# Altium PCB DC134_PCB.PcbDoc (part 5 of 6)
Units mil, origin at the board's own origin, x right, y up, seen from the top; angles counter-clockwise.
Board outline 4000 x 2750 mil, 6 copper layers (L1_Top Layer, L2_GND1, L3_Signal, L4_Plane, L5_GND2, L6_Bottom Layer), stack 60.4 mil thick; 404 components, 244 nets, 1547 pads, 694 vias.
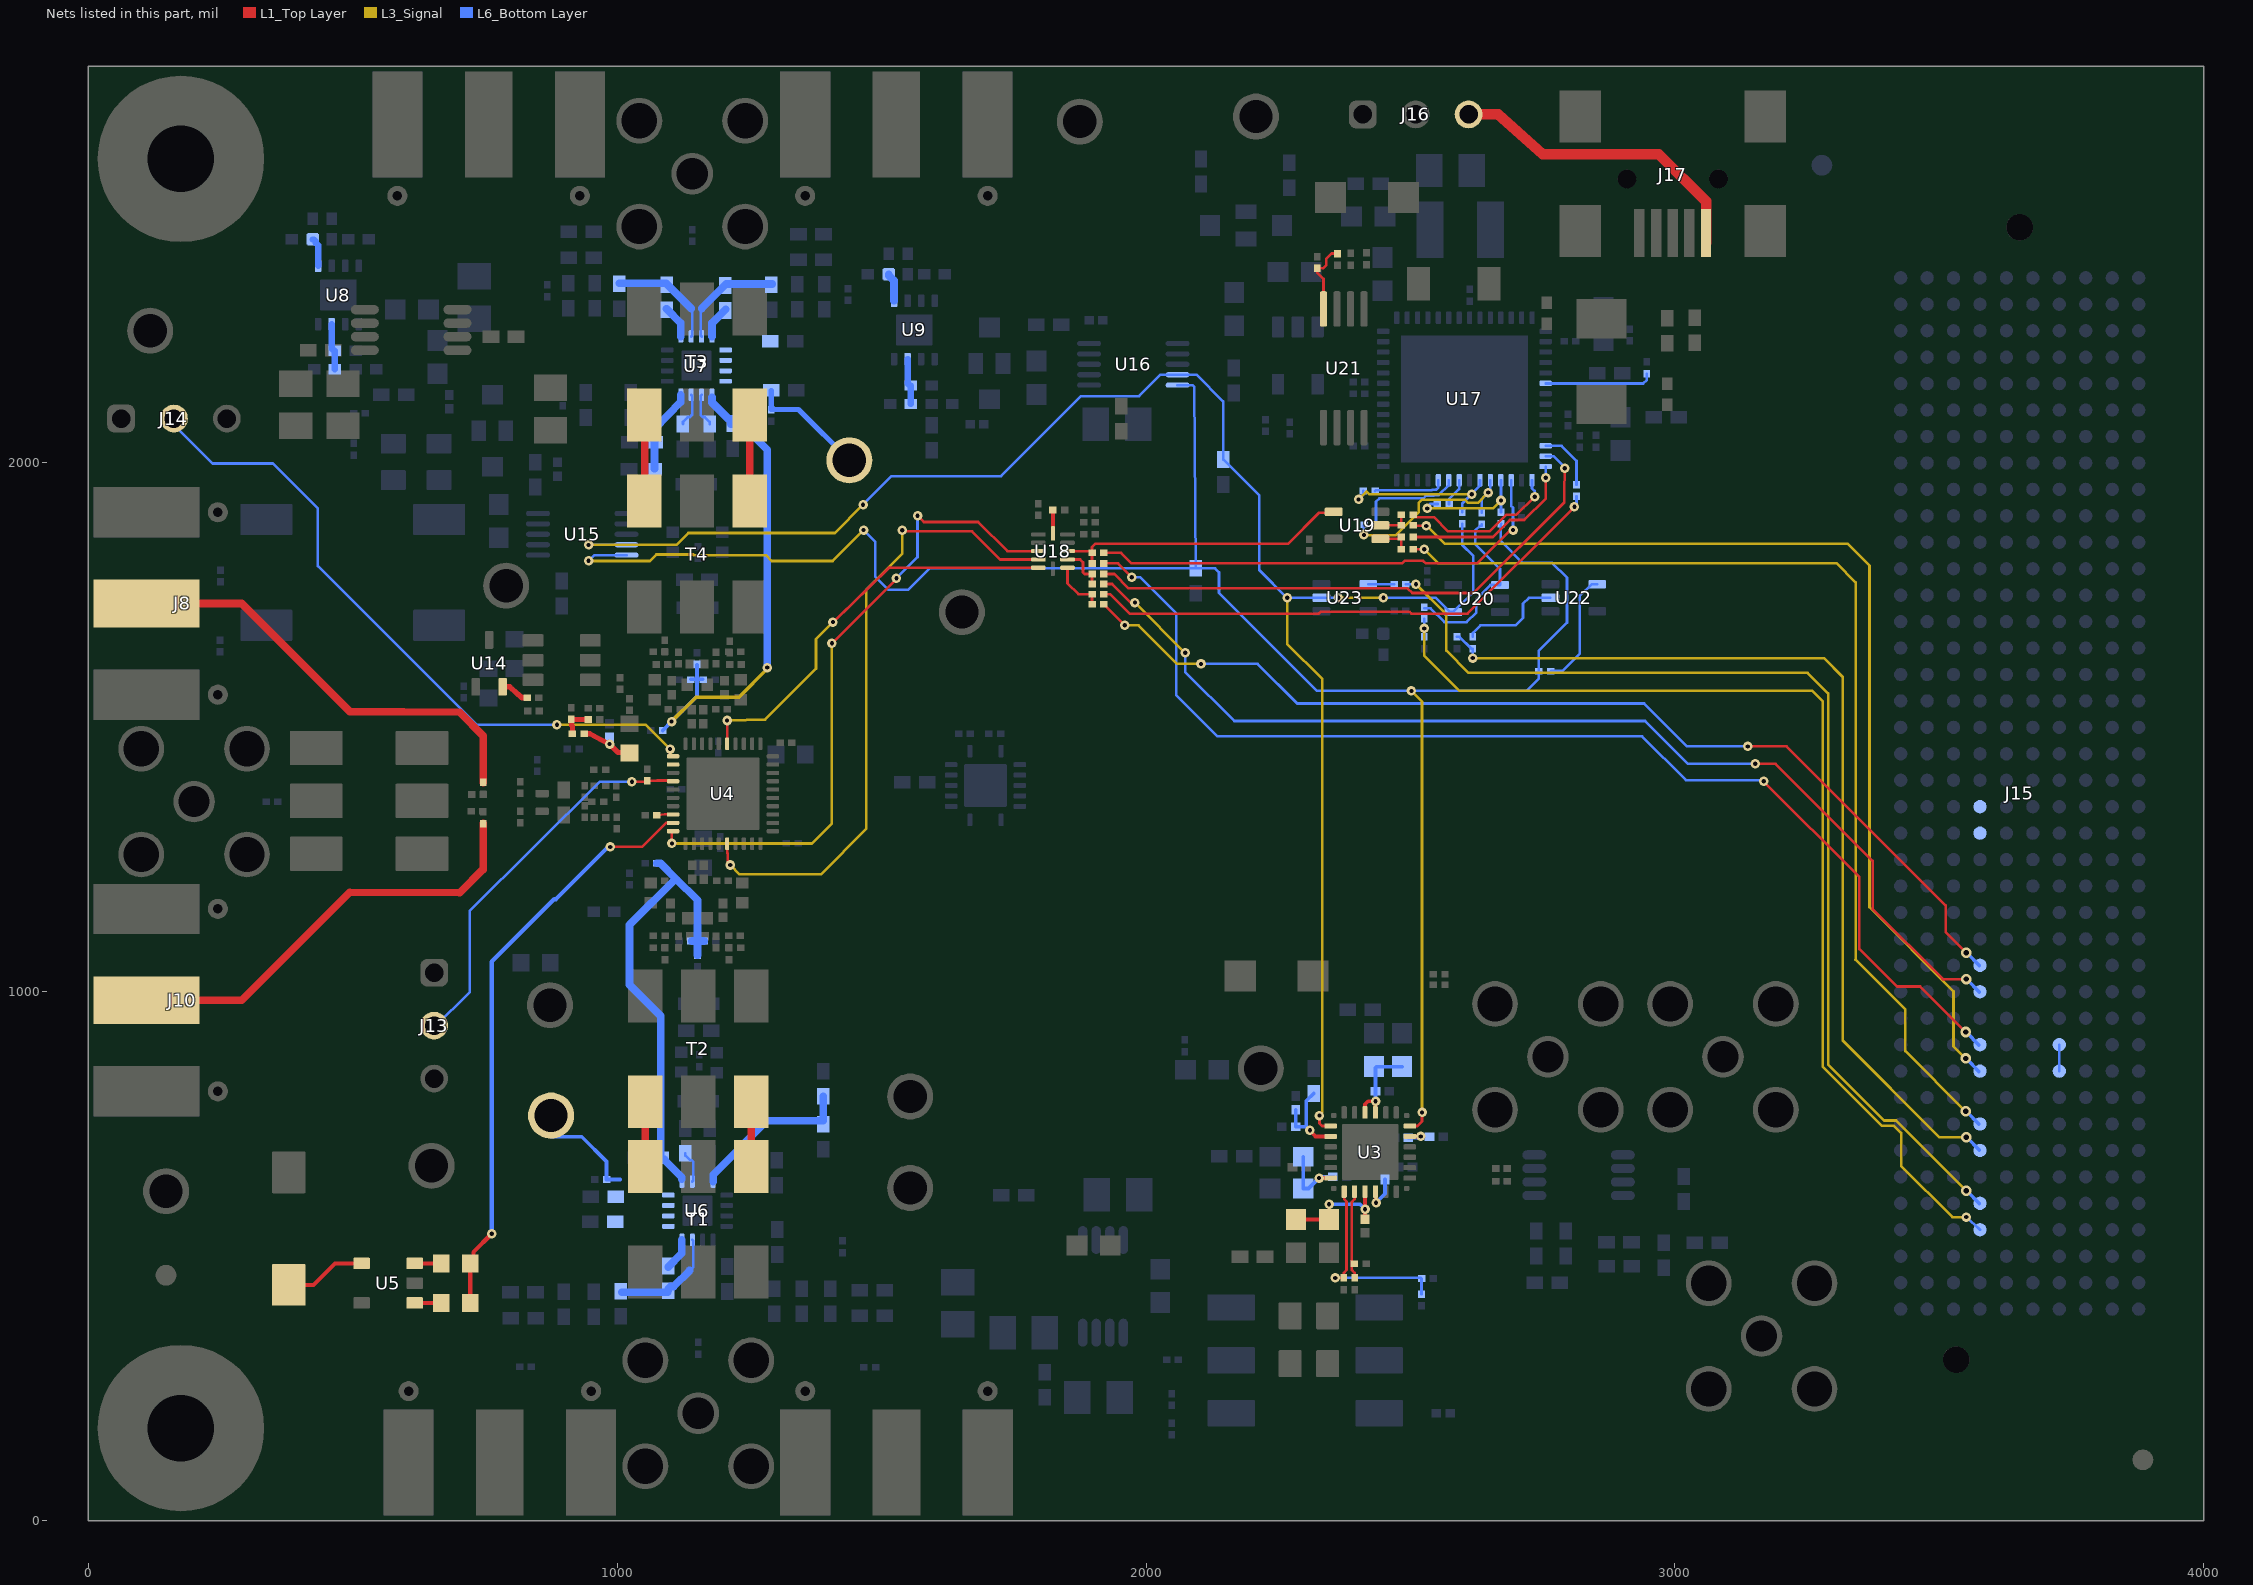
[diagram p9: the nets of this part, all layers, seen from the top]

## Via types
v1: diameter 18, hole 8, L1_Top Layer to L6_Bottom Layer, tented both sides, 448 vias
v2: diameter 20, hole 10, L1_Top Layer to L6_Bottom Layer, tented both sides, 182 vias
v3: diameter 19.68, hole 7.87, L1_Top Layer to L6_Bottom Layer, tented both sides, 42 vias
v4: diameter 19.68, hole 7.87, L1_Top Layer to L6_Bottom Layer, 20 vias
v5: diameter 18, hole 8, L1_Top Layer to L6_Bottom Layer, 2 vias

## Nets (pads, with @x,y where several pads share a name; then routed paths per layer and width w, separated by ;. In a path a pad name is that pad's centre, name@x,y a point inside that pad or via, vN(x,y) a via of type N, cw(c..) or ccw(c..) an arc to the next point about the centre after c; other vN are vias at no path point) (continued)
NetR88_2: R88.2 R96.1 U6.3 | length 207.5
  L6_Bottom Layer w5: 1136.93,472.86 1144,479.93 1144,529.08 U6.3@1142.08,531
  L6_Bottom Layer w14.5: R88.2@1008.45,431.62 R96.1@1095.69,431.62 ; R96.1@1096.8,434.38 1096.8,438.32 1101.36,442.88 1106.95,442.88 1136.93,472.86
NetR90_1: R90.1 U6.10 | length 61.8
  L6_Bottom Layer w5: R90.1@1129,694.38 1129,690.44 1138.31,681.13 1141.07,681.13 1144,678.2 1144,643.16 U6.10@1142.08,641.24
NetR96_2: R96.2 U6.4 | length 62.1
  L6_Bottom Layer w14.5: R96.2@1096.45,479.62 1122.39,505.57 U6.4@1122.39,531
NetR97_1: R97.1 R103.2 U7.2 | length 208.9
  L6_Bottom Layer w5: U7.2@1140,2239.12 1142,2241.12 1142,2290.06 1140,2292.06
  L6_Bottom Layer w14.5: R103.2@1004.32,2339.5 R97.1@1092.56,2339.5 ; R97.1@1093.32,2338.74 1140,2292.06
NetR97_2: R97.2 U7.1 | length 63.6
  L6_Bottom Layer w14.5: R97.2@1093.32,2291.5 1120.32,2264.5 U7.1@1120.32,2239.12
NetR101_1: R101.1 U7.11 | length 65.7
  L6_Bottom Layer w5: R101.1@1124.45,2073.62 1124.45,2077.56 1133.76,2086.87 1137.7,2086.87 1142,2091.17 1142,2126.88 U7.11@1140,2128.88
NetR105_2: R105.2 R113.1 U7.3 | length 206.3
  L6_Bottom Layer w5: U7.3@1159.69,2239.12 1157.79,2241.01 1157.79,2290.22 1159.69,2292.11
  L6_Bottom Layer w14.5: 1159.69,2292.11 R113.1@1205.32,2337.74 ; R113.1@1206.07,2338.5 R105.2@1293.32,2338.5
NetR107_1: R107.1 U7.10 | length 65.4
  L6_Bottom Layer w5: U7.10@1159.69,2128.88 1157.79,2126.99 1157.79,2090.73 1161.65,2086.87 1165.59,2086.87 1174.9,2077.56 R107.1@1174.9,2073.62
NetR113_2: R113.2 U7.4 | length 62.1
  L6_Bottom Layer w14.5: U7.4@1179.37,2239.12 1179.37,2264.55 R113.2@1205.32,2290.5
NetR116_1: R116.1 R121.2 U8.5 | length 55.3
  L6_Bottom Layer w12: R121.2@424.48,2422.62 426.45,2422.62 430.29,2418.78 430.29,2415.94 434.48,2411.75 U8.5@434.48,2372.62
NetR118_1: R118.1 R122.2 U9.5 | length 54.1
  L6_Bottom Layer w15: R118.1@1513.61,2356.65 1513.61,2354.68 1523.61,2344.68 U9.5@1523.61,2306.65
NetR119_1: R119.1 R175.2 U8.3 | length 88.7
  L6_Bottom Layer w12: U8.3@460.07,2262.39 460.07,2223.26 460.36,2222.97 460.36,2216.23 464.2,2212.39 R119.1@466.17,2212.39 R175.2@466.17,2177.39
NetR120_1: R120.1 R176.2 U9.3 | length 88.7
  L6_Bottom Layer w12: U9.3@1549.2,2196.41 1549.2,2157.28 1549.5,2156.99 1549.5,2150.25 1553.34,2146.41 R120.1@1555.31,2146.41 R176.2@1555.31,2111.41
NetR128_2: R128.2 R129.2 R130.1 | length 59.8
  L1_Top Layer w10: R130.1@915.48,1487.98 915.48,1502 913.5,1503.98 R129.2@913.5,1514.95 R128.2@945.48,1514.95
NetR131_1: R131.1 U14.2 | length 54.3
  L1_Top Layer w10: U14.2@783.59,1576.71 797,1576.71 819.98,1556.02 R131.1@829.98,1556.02
NetR135_2: R135.2 R141.2 U18.7 | length 103.2
  L1_Top Layer w5: U18.7@1851.56,1801.8 1851.56,1772.44 1872,1752 R141.2@1897.98,1752 R135.2@1897.98,1733
NetR136_2: R136.2 R142.2 U18.8 | length 88
  L1_Top Layer w5: U18.8@1851.56,1817.54 1875.46,1817.54 1881,1812 1881,1793 1884,1790 R142.2@1897.98,1790 R136.2@1897.98,1771
NetR137_2: R137.2 R143.2 U19.1 | length 57.9
  L1_Top Layer w5: U19.1@2443.29,1856.41 2482.39,1856.41 R137.2@2482.39,1837.59
NetR138_2: R138.2 R144.2 U19.2 | length 59.7
  L1_Top Layer w5: U19.2@2443.29,1882 R138.2@2482.98,1882 R144.2@2482.98,1902
NetR139_2: R139.2 R146.2 U18.9 U19.4 | length 563.1
  L1_Top Layer w5: U18.9@1851.56,1833.29 1894.69,1833.29 R146.2@1897.98,1830 ; R139.2@1897.98,1810 R146.2@1897.98,1830 ; U19.4@2354.71,1907.59 2352.71,1905.59 2326.67,1905.59 2268.07,1847 1904,1847 1897.98,1840.98 R146.2@1897.98,1830
NetR140_1: R140.1 U17.12 | length 115.2
  L6_Bottom Layer w5: U17.12@2755.56,2032.42 2785.58,2032.42 2814,2004 R140.1@2814,1959.02
NetR140_2: R140.2 R141.1 | length 1013.5
  L1_Top Layer w5: R141.1@1920.02,1752 1932,1752 1969,1715 2326.67,1715 2330.17,1718.5 2498.52,1718.5 2502.02,1715 2608,1715 v1(2810,1917)
  L6_Bottom Layer w5: v1(2810,1917) 2814,1921 R140.2@2814,1936.98
NetR142_1: R142.1 U17.13 | length 1067.7
  L1_Top Layer w5: R142.1@1920.02,1790 1940,1790 1967,1763 2494.67,1763 2503.55,1754.11 2619.45,1754.11 2791,1925.67 2791,1942 v1(2792,1990)
  L6_Bottom Layer w5: U17.13@2755.56,2012.73 2770.27,2012.73 2792,1991 v1(2792,1990)
NetR143_1: R143.1 U17.14 | length 341.2
  L1_Top Layer w5: R143.1@2505.02,1860 2656,1860 2688,1892 2693.67,1892 ; 2693.76,1892 2715,1892 2756,1933 v1(2756,1972)
  L6_Bottom Layer w5: U17.14@2755.56,1993.05 2755.56,1986.44 v1(2756,1972)
NetR144_1: R144.1 U17.15 | length 303.4
  L1_Top Layer w5: R144.1@2505.02,1902 2509.52,1897.5 2544.5,1897.5 2571.46,1870.54 2649.57,1870.54 2681.02,1902 2700,1902 v1(2735,1936)
  L6_Bottom Layer w5: U17.15@2730,1967.43 2730,1952 2735,1947 v1(2735,1936)
NetR145_1: R145.1 U17.22 | length 53.8
  L6_Bottom Layer w5: R145.1@2573.02,1921.57 2573.02,1931.53 2592.18,1950.69 U17.22@2592.18,1967.46
NetR145_2: R145.2 R158.1 U17.18 | length 245.4
  L3_Signal w5: v1(2532,1914) 2656.29,1914 v1(2671.29,1929)
  L6_Bottom Layer w5: v1(2532,1914) 2532,1917 v1@2536.57,1921.57 ; R145.2@2550.97,1921.57 v1@2536.57,1921.57 ; R145.2@2551.66,1922.34 2537.34,1922.34 v1@2536.57,1921.57 ; U17.18@2670.92,1967.46 2671.29,1967.08 R158.1@2671.29,1907.02
NetR146_1: R146.1 U17.17 | length 909.8
  L1_Top Layer w5: R146.1@1920.02,1830 1953,1830 1973,1810 2484,1810 2489,1815 2524,1815 2529,1810 2626,1810 2690.78,1874.78 2692.56,1873 v1(2694,1873)
  L6_Bottom Layer w5: U17.17@2690.6,1967.46 2690.6,1919 2694,1915.6 v1(2694,1873)
NetR148_1: R148.1 U17.23 | length 203.5
  L6_Bottom Layer w5: R148.1@2435.02,1883 2435.02,1927 2441.22,1933.2 2524.87,1933.2 2529.81,1938.15 2544.14,1938.15 2545.49,1939.5 2553.5,1939.5 2572.49,1958.49 U17.23@2572.49,1967.46
NetR148_2: R148.2 R159.1 U17.19 | length 372.2
  L3_Signal w5: v1(2412,1864) 2412,1863 2472,1863 2515.5,1906.5 2515.5,1923.83 2522.17,1930.5 2603.17,1930.5 2609.17,1924.5 2627.5,1924.5 v1(2647,1944)
  L6_Bottom Layer w5: v1(2412,1864) 2412,1882.02 R148.2@2412.98,1883 ; R159.1@2635,1906.02 2635,1932 v1(2647,1944) 2651.23,1948.23 U17.19@2651.23,1967.46
NetR149_1: R149.1 U18.12 | length 44.2
  L1_Top Layer w7: U18.12@1824,1866.76 R149.1@1823.98,1911
NetR151_1: R151.1 U17.24 | length 136.5
  L6_Bottom Layer w5: R151.1@2433.02,1947 2434.17,1948.15 2539.99,1948.15 2541.35,1949.5 2548.84,1949.5 2552.8,1953.46 U17.24@2552.8,1967.46
NetR151_2: R151.2 R163.1 U17.20 | length 316.3
  L3_Signal w5: v1(2402,1931) 2417,1946 2422,1941 v1(2616,1941)
  L6_Bottom Layer w5: v1(2402,1931) 2410.98,1939.98 R151.2@2410.98,1947 ; R163.1@2598,1907.02 2598,1923.55 2631.55,1957.09 U17.20@2631.55,1967.46
NetR154_2: R154.2 U17.6 | length 206.6
  L6_Bottom Layer w5: U17.6@2755.56,2150.53 2755.56,2150.19 2940.17,2150.19 2947,2157.02 R154.2@2947,2168.98
NetR159_2: R159.2 R169.2 U20.1 | length 339
  L6_Bottom Layer w5: R169.2@2526,1725.02 2537.98,1725.02 2564,1699 2606.08,1699 2624.5,1717.42 2624.5,1742.5 2651.21,1769.21 U20.1@2669.4,1769.21 2669.4,1799.6 2622.5,1846.5 2622.5,1871.83 2632.17,1881.5 2635,1881.5 R159.2@2635,1883.98
NetR162_1: R162.1 R164.1 U21.4 | length 138.5
  L1_Top Layer w5: U21.4@2335.61,2291.2 2335.61,2348 2324,2359.61 R162.1@2324,2367.98 2334.98,2367.98 2340.59,2373.59 2340.59,2386 2350.64,2396.05 R164.1@2362,2396.02
NetR167_2: R167.2 U22.2 | length 197.6
  L6_Bottom Layer w5: R167.2@2618,1671.02 2618,1678.65 2632.35,1693 2699,1693 2713,1707 2713,1734 2724,1745 U22.2@2764.71,1745
NetR168_1: R168.1 U22.4 | length 220.3
  L6_Bottom Layer w5: R168.1@2765.02,1606 2766.02,1607 2788,1607 2820,1639 2820,1748 2842.59,1770.59 U22.4@2853.29,1770.59
NetR170_2: R170.2 U23.4 | length 48.7
  L6_Bottom Layer w5: U23.4@2420.29,1770.61 R170.2@2468.98,1770.61
NetR171_1: R171.1 U5.1 | length 50
  L1_Top Layer w8: U5.1@617.2,411.6 R171.1@667.2,411.6
NetR172_1: R172.1 U5.3 | length 50
  L1_Top Layer w8: U5.3@617.2,486.4 R172.1@667.2,486.4
NetS1_2: S1.2 U5.4 | length 154.7
  L1_Top Layer w8: S1.2@379,445.7 425.7,445.7 466.4,486.4 U5.4@516.8,486.4
NetT1_4: T1.4 T2.6 | length 122
  L1_Top Layer w14.5: T1.4@1253.37,670 T2.6@1253.37,792
NetT1_6: T1.6 T2.4 | length 122
  L1_Top Layer w14.5: T1.6@1053.37,670 T2.4@1053.37,792
NetT3_4: T3.4 T4.6 | length 164.7
  L1_Top Layer w14.5: T4.6@1051,1927.76 1052.02,1928.78 T3.4@1052.02,2092
NetT3_6: T3.6 T4.4 | length 163.2
  L1_Top Layer w14.5: T4.4@1251,1927.76 T3.6@1251,2091
OE: R72.1 R74.2 U3.11 | length 45.2
  L1_Top Layer w7: U3.11@2498.8,726.53 v1(2519.47,726.53)
  L6_Bottom Layer w7: R74.2@2495.99,724 2516.94,724 v1(2519.47,726.53)
PD_AMP_CHA: R85.1 R89.2 U6.12 | length 309.3
  L6_Bottom Layer w14.5: U6.12@1181.45,641.24 1181.45,654 1283,756 1389.38,756 1390,756.62 R89.2@1390,802
PD_AMP_CHB: R102.1 R106.2 U7.12 | length 160.2
  L6_Bottom Layer w14.5: R102.1@1070.52,1989 R106.2@1070.52,2039 1071,2039.48 1071,2065 1120.32,2115.32 U7.12@1120.32,2128.88
PDN_SYNC: J14.2 U4.1 | length 1263
  L1_Top Layer w5: U4.1@1100,1444.72 v1(1100,1459)
  L3_Signal w5: v1(886,1505) 1054,1505 v1(1100,1459)
  L6_Bottom Layer w5: J14.2@167,2067 235,1999 349,1999 434,1914 434,1805 734,1505 v1(886,1505)
PDN_SYNC_FPGA: J15.G21
REFBUF: C45.1 J13.2 U4.4 | length 733.9
  L1_Top Layer w5: v1(1028,1397) 1055.02,1397 C45.1@1057,1398.98 1075.14,1398.98 1075.67,1399.5 1104.63,1399.5 U4.4@1105.51,1398.62 ; U4.4@1103.54,1398.62 U4.4@1103.54,1398.84
  L6_Bottom Layer w5: J13.2@655,933 721,999 721,1153 967,1397 v1(1028,1397)
REFSEL: R62.2 U3.4 | length 72.1
  L1_Top Layer w7: U3.4@2433.84,622.2 2435,621.04 v1(2435,601.3)
  L6_Bottom Layer w7: v1(2435,601.3) 2452,618.3 R62.2@2452,645.01
RESET: R171.2 R172.2 U4.9 | length 1113.7
  L1_Top Layer w5: v1(987,1274) 1047,1274 1092.88,1319.88 U4.9@1105.51,1319.88
  L1_Top Layer w8: R171.2@722.32,411.6 R172.2@722.32,486.4 728.14,492.23 728.14,507.7 v1(763,542.56)
  L6_Bottom Layer w8: v1(763,542.56) 763,1057 881.17,1175.17 884.17,1175.17 983,1274 v1(987,1274)
RESET_FPGA: J15.G22
SCL_I2C: R156.1 R158.2 R168.2 U3.12 U15.5 U16.5 | length 3762.4
  L1_Top Layer w5: U3.12@2498.8,746.21 2513.21,746.21 2522,755 v1(2522,772)
  L3_Signal w5: v1@946.41,1814.59 1061.7,1814.59 1074,1826.89 1143.77,1826.89 1145.17,1825.5 1281.39,1825.5 1292.3,1814.59 1407.59,1814.59 v1(1466,1873) ; v1(2502,1569) 2522,1549 v1(2522,772)
  L6_Bottom Layer w5: v1(946,1815) 956.71,1825.71 U15.5@1017.66,1825.71 ; v1(1466,1873) 1488,1851 1488,1785 1513,1760 1550,1760 1590.62,1800.62 R156.1@2094,1800.62 ; U16.5@2059.66,2147.13 2088.2,2147.13 2091,2144.33 R156.1@2094,1800.62 ; R158.2@2671.29,1884.98 2670.92,1884.6 2670.92,1852 2711.92,1811 2768,1811 2796,1783 2796,1698 2742.98,1644.98 2742.98,1592.6 2719.38,1569 v1(2502,1569) 2323,1569 2138,1754 2138,1793 2130.38,1800.62 R156.1@2094,1800.62
SCL_I2C_FPGA: J15.G34 R165.2 R167.1 | length 1802.9
  L3_Signal w5: v1(2618,1631) 3282,1631 3317.5,1595.5 3317.5,907.5 3499.85,725.15 v2(3551,725.15)
  L6_Bottom Layer w5: R165.2@2588,1671.02 2592.98,1671.02 2615.02,1648.98 R167.1@2618,1648.98 v1(2618,1631)
  L6_Bottom Layer w6.6: v2@3552,725.15 J15.G34@3576,700.3
SCLK: U4.35 U18.5 | length 785.1
  L1_Top Layer w5: U4.35@1207.87,1469.49 v1@1207.87,1515 ; v1(1408,1699) v1@1408.89,1699 ; v1@1409,1699 v1@1408.89,1699 ; U18.5@1796.44,1801.8 1514.2,1801.8 1408.94,1699.06 v1@1408.89,1699
  L3_Signal w5: v1(1207.87,1513) 1280,1515 1376,1611 1376,1667 v1(1408,1699)
SCLK_FPGA: J15.G27 R135.1 | length 1967.9
  L1_Top Layer w5: R135.1@1920.02,1733 v1(1960.02,1693) ; v1(3138,1464) 3211.18,1464 3512,1163.18 3512,1113 v2(3551,1074)
  L3_Signal w5: v1(1960.02,1693) 1986,1693 2059,1620 v1(2104,1620)
  L6_Bottom Layer w5: v1(2104,1620) 2211,1620 2286,1545 2942,1545 3023,1464 v1(3138,1464)
  L6_Bottom Layer w6.6: v2@3552,1074 J15.G27@3576,1049.15
SDA_I2C: R157.1 R163.2 U3.19 U15.4 U16.4 U20.4 U23.2 | length 3411.4
  L1_Top Layer w5: v1(2328,766) 2328,751 2332.79,746.21 U3.19@2349.2,746.21
  L3_Signal w5: v1(946,1845) 1112,1845 1134.5,1867.5 1411.5,1867.5 v1(1465,1921) ; v1(2267,1745.02) 2267,1658 2333.5,1591.5 2333.5,771.5 v1(2328,766) ; v1(2363.98,1745.02) v1(2449.02,1745.02)
  L6_Bottom Layer w5: v1(946,1845) 946.39,1845.39 U15.4@1017.66,1845.39 ; v1(1465,1921) 1519.01,1975.01 1726.01,1975.01 1877.25,2126.25 1986.75,2126.25 2027.32,2166.81 U16.4@2059.66,2166.81 2095.68,2166.81 2146,2116.5 R157.1@2146,2007 ; R157.1@2146,2006.62 R157.1@2146,2007 ; v1(2363.98,1745.02) U23.2@2331.71,1745.02 v1(2267,1745.02) 2214,1798.02 2214,1939 R157.1@2146,2007 ; v1(2449.02,1745.02) 2547.93,1745.02 2574.92,1718.03 U20.4@2580.82,1718.03 2619,1756.21 2619,1824 2598,1845 R163.2@2598,1884.98
SDA_IN_I2C_FPGA: J15.G36 R170.1 | length 2020.4
  L3_Signal w5: v1(2510.39,1770.61) 2568,1713 2568,1645 2610,1603 3251,1603 3290,1564 3290,862.25 3395.75,756.5 3418.5,756.5 v2(3551,624)
  L6_Bottom Layer w5: R170.1@2491.02,1770.61 v1(2510.39,1770.61)
  L6_Bottom Layer w6.6: v2@3552,624 J15.G36@3576,599.15
SDA_OUT_I2C_FPGA: J15.G37 R166.2 R169.1 | length 2026.3
  L3_Signal w5: v1(2526,1687) 2526,1636 2593,1569 3260,1569 3280,1549 3280,858.11 3391.61,746.5 3414.36,746.5 3428,732.86 3428,671 3525,574 v1(3551,574)
  L6_Bottom Layer w5: R166.2@2526,1671.02 v1(2526,1687) R169.1@2526,1705.09 ; v1(3551,574) J15.G37@3577,550
SDIO: U4.10 U18.3 | length 1247.9
  L1_Top Layer w5: v1(1103.54,1280.46) 1103.54,1302.17 U4.10@1105.51,1304.13 ; v1(1406,1659) 1528,1781 v1(1528,1782) ; v1(1568,1900.15) 1579.85,1888.29 1682.71,1888.29 1737.71,1833.29 U18.3@1796.44,1833.29
  L3_Signal w5: v1(1103.54,1280.46) 1368.46,1280.46 1406,1318 v1(1406,1659)
  L6_Bottom Layer w5: v1(1528,1782) 1568,1822 v1(1568,1900.15)
SDIO_I_FPGA: J15.G31 R138.1 | length 1936.4
  L1_Top Layer w5: R138.1@2505.02,1882 2506.02,1881 v1(2530,1881)
  L3_Signal w5: v1(2530,1881) 2531,1881 2565.04,1846.96 3071.93,1846.96 3071.97,1847 3327,1847 3368,1806 3368,1160 3527,1001 3527,897 v2(3550,874)
  L6_Bottom Layer w6.6: v2@3551,874 J15.G31@3575,849.15
SDIO_O_FPGA: J15.G30 R139.1 | length 2203.2
  L1_Top Layer w5: R139.1@1920.02,1810 1946.98,1810 v1(1972.98,1784) ; v1(3168,1398) 3349,1217 3349,1081 3420,1010 3464,1010 v2(3550,924)
  L6_Bottom Layer w5: v1(1972.98,1784) 1989,1784 2057,1716 2057,1561 2135,1483 2938,1483 3020.85,1400.15 3168,1400.15 v1(3168,1398)
  L6_Bottom Layer w6.6: v2@3551,924 J15.G30@3575,899.15
SDIO_OE_FPGA: J15.G33 R137.1 | length 1984.1
  L1_Top Layer w5: R137.1@2505.02,1837 v1(2526,1837)
  L3_Signal w5: v1(2526,1837) 2552.34,1810.66 3305.34,1810.66 3342,1774 3342,1061 3341.66,1060.66 3436,966.31 3436,888 v2(3550,774)
  L6_Bottom Layer w6.6: v2@3551,774 J15.G33@3575,749.15
SECREF_N: R63.1 R70.1 U3.2 | length 167.5
  L1_Top Layer w5: R63.1@2394.47,459.02 2394.47,468.61 2389.24,473.85 2389.24,602.65 2394.47,607.89 U3.2@2394.47,622.2
SECREF_P: R60.1 R65.2 R67.2 U3.1 | length 376.8
  L1_Top Layer w5: v1(2357.65,459.02) R60.1@2374,459.02 2374,468.61 2379.24,473.85 2379.24,603.44 2374.79,607.89 U3.1@2374.79,622.2
  L6_Bottom Layer w5: v1(2357.65,459.02) 2519.25,459.02 2520.87,457.4 R65.2@2520.87,428.02
SEN: U4.16 U18.4 | length 1215.6
  L1_Top Layer w5: U4.16@1207.99,1280.06 1207.99,1262.46 1209.06,1261.39 1209.06,1244.7 v1(1214,1239.76) ; v1(1539,1872.54) 1541,1870.54 1671,1870.54 1724,1817.54 U18.4@1796.44,1817.54
  L3_Signal w5: v1(1214,1239.76) 1231.7,1222.06 1385.06,1222.06 1471,1308 1471,1760 1539,1828 v1(1539,1872.54)
SEN_FPGA: J15.G28 R136.1 | length 2049
  L1_Top Layer w5: R136.1@1920.02,1771 1936,1771 1971,1736 v1(1979,1736) ; v1(3152,1431) 3190.41,1431 3374,1247.41 3374,1157 3507,1024 v2(3551,1024)
  L3_Signal w5: v1(1979,1736) v1(2074,1641)
  L6_Bottom Layer w5: v1(2074,1641) 2074,1605 2167,1512 2944,1512 3025,1431 v1(3152,1431)
  L6_Bottom Layer w6.6: v2@3552,1024 J15.G28@3576,999.15
SMA_CLK_N: J10.1 R51.1 | length 833.3
  L1_Top Layer w14.5: J10.1@105,984.25 133,984.25 290.36,984.25 494.61,1188.5 702,1187.15 747.02,1232.18 ; 747.02,1230.9 747.02,1232.18 ; R51.1@747.02,1318.94 747.02,1298.18 747.02,1232.18
SMA_CLK_P: J8.1 R45.1 | length 833.3
  L1_Top Layer w14.5: J8.1@105,1734.25 133,1734.25 290.36,1734.25 494.61,1530 702,1528.65 747.02,1483.63 747.02,1416.35 R45.1@747.02,1395.59
STATUS: R56.1 R58.2 R59.2 U3.20 | length 164.8
  L1_Top Layer w7: v1(2310,738) 2320.47,726.53 U3.20@2349.2,726.53
  L6_Bottom Layer w7: R56.1@2283,777.01 R58.2@2282.99,745 2303,745 2303,793.76 R59.2@2317,807.76
TDI_TDO: J15.D30 J15.D31 | length 50
  L6_Bottom Layer w5: J15.D31@3727,850 J15.D30@3727,900
USB_+5Vin: J16.3 J17.1 | length 592.8
  L1_Top Layer w20: J16.3@2610,2659 2666,2659 2750,2584 2969.91,2584 3058.99,2494.91 J17.1@3058.99,2434.64 J17.1@3058.99,2416.64
VCM: R75.2 U4.8 | length 26.7
  L1_Top Layer w5: R75.2@1076.87,1333.62 1089.75,1335.5 U4.8@1103.41,1335.5
VCM_FDA_CHA: C5.2 C50.2 R7.1 R8.2 R76.2 U6.9 | length 874.5
  L6_Bottom Layer w14.5: R76.2@1075.02,1243 1082,1243 1111,1214 ; C50.2@1082.62,686 1082.62,954.19 1023.37,1013.44 1023.37,1126.37 1111,1214 ; C50.2@1088.44,683 1089.56,683 1091.12,681.44 1091.12,680.32 1122.39,649.05 U6.9@1122.39,645.8 ; R8.2@1141.02,1096 R7.1@1164.67,1096 ; 1151.92,1096 1152,1095.92 ; C5.2@1152,1069.02 1152,1173 1111,1214
VCM_FDA_CHB: C13.2 C55.2 R21.1 R22.2 R77.2 U7.9 | length 970.7
  L3_Signal w7: v1(1103,1510.98) 1149.02,1557 1230.25,1557 1284,1610.75 v1(1284,1613)
  L6_Bottom Layer w7: R77.2@1086.02,1494 v1(1103,1510.98) 1151,1558.98 1151,1591 ; R21.1@1139.32,1591 1151,1591 ; C13.2@1151,1617.98 1151,1591 ; R22.2@1162.02,1591 1151,1591
  L6_Bottom Layer w14.5: U7.9@1179.37,2124.32 1179.37,2114.25 1210.5,2083.12 1214.44,2083.12 1219,2078.56 C55.2@1219,2074.62 ; C55.2@1214.81,2073.62 1229.76,2073.62 1228.76,2074.62 1234.38,2074.62 1242,2067 1284,2025 v1(1284,1613)
VDD_REF: C28.1 C29.1 L8.2 U3.3 | length 215.2
  L1_Top Layer w7: L8.2@2283.89,569.5 C28.1@2346.26,569.5 v1(2346.26,598.26) ; C29.1@2414.16,569.99 v1(2414.16,588.68) U3.3@2414.16,622.2
  L6_Bottom Layer w7: v1(2346.26,598.26) 2404.57,598.26 v1(2414.16,588.68)
VDD_VCO: C32.1 C33.1 L9.2 U3.24 | length 147.2
  L1_Top Layer w7: v1(2327.21,647.79) U3.24@2349.2,647.79
  L6_Bottom Layer w7: L9.2@2297.44,688 C32.1@2297.44,628 2307.43,628 v1(2327.21,647.79) 2329.57,650.15 C33.1@2353.51,650.15
VDDO_12: C35.1 C36.1 L10.2 U3.15 U3.16 | length 173.1
  L1_Top Layer w7: U3.16@2414.16,771.8 2414.16,787.16 2420.01,793.01 v1(2434.01,793.01) 2434.01,771.97 U3.15@2433.84,771.8
  L6_Bottom Layer w7: v1(2434.01,793.01) C36.1@2434.01,811.75 2434.01,855.7 2436.81,858.5 C35.1@2484.32,858.5
VREF: C44.1 R79.2 R130.2 U4.2 | length 98.9
  L1_Top Layer w10: R130.2@937.52,1487.98 948.02,1487.98 v1(985.71,1468.29) 1001.56,1452.44 C44.1@1025,1452.44
VS+_CHA: C65.1 C66.1 R93.1 TP9.1 U6.5 U6.6 U6.7 U6.8 | length 184.5
  L6_Bottom Layer w7: TP9.1@875,726 933,726 980.02,678.98 R93.1@980.02,645 1006,645
VS+_CHB: C63.1 C64.1 R108.1 TP11.1 U7.5 U7.6 U7.7 U7.8 | length 223.3
  L6_Bottom Layer w10: R108.1@1291.38,2101.02 1342.98,2101.02 TP11.1@1439,2005 ; R108.1@1291.38,2101.14 C64.1@1291.38,2137
pads on no net: FID1.1 FID2.1 FID3.1 H1.1 H2.1 H3.0 H4.0 J15.A2 J15.A3 J15.A6 J15.A7 J15.A10 J15.A11 J15.A14 J15.A15 J15.A18 J15.A19 J15.A22 J15.A23 J15.A26 J15.A27 J15.A30 J15.A31 J15.A34 J15.A35 J15.A38 J15.A39 J15.B1 J15.B4 J15.B5 J15.B8 J15.B9 J15.B12 J15.B13 J15.B16 J15.B17 J15.B20 J15.B21 J15.B24 J15.B25 J15.B28 J15.B29 J15.B32 J15.B33 J15.B36 J15.B37 J15.B40 J15.C2 J15.C3 J15.C6 J15.C7 J15.C10 J15.C11 J15.C14 J15.C15 J15.C18 J15.C19 J15.C22 J15.C23 J15.C26 J15.C27 J15.C30 J15.C31 J15.C34 J15.C35 J15.C37 J15.C39 J15.D1 J15.D4 J15.D5 J15.D8 J15.D9 J15.D11 J15.D12 J15.D14 J15.D15 J15.D17 J15.D18 J15.D20 J15.D21 J15.D23 J15.D24 J15.D26 J15.D27 J15.D29 J15.D32 J15.D33 J15.D34 J15.D35 J15.D36 J15.D38 J15.D40 J15.E18 J15.E19 J15.E21 J15.E22 J15.E24 J15.E25 J15.E27 J15.E28 J15.E30 J15.E31 J15.E33 J15.E34 J15.E36 J15.E37 J15.E39 J15.F1 J15.F7 J15.F8 J15.F10 J15.F11 J15.F13 J15.F14 J15.F16 J15.F17 J15.F19 J15.F20 J15.F22 J15.F23 J15.F25 J15.F26 J15.F28 J15.F29 J15.F31 J15.F32 J15.F34 J15.F35 J15.F37 J15.F38 J15.F40 J15.G2 J15.G3 J15.G7 J15.G9 J15.G10 J15.G12 J15.G13 J15.G15 J15.G16 J15.G18 J15.G19 J15.G24 J15.G25 J15.H1 J15.H5 J15.H7 J15.H8 J15.H10 J15.H11 J15.H13 J15.H14 J15.H16 J15.H17 J15.H19 J15.H20 J15.H22 J15.H23 J15.H25 J15.H26 J15.H28 J15.H29 J15.H31 J15.H32 J15.H34 J15.H35 J15.H37 J15.H38 J15.H40 J15.J2 J15.J3 J15.J6 J15.J7 J15.J9 J15.J10 J15.J12 J15.J13 J15.J15 J15.J16 J15.J18 J15.J19 J15.J21 J15.J22 J15.J24 J15.J25 J15.J27 J15.J28 J15.J30 J15.J31 J15.J33 J15.J34 J15.J36 J15.J37 J15.J39 J15.K1 J15.K4 J15.K5 J15.K7 J15.K8 J15.K10 J15.K11 J15.K13 J15.K14 J15.K19 J15.K20 J15.K22 J15.K23 J15.K25 J15.K26 J15.K28 J15.K29 J15.K31 J15.K32 J15.K34 J15.K35 J15.K37 J15.K38 J15.K40 J15.MH1 J15.MH2 J17.4 J17.10 J17.11 LBL1.0 T1.2 T2.2 T3.2 T4.2 T5.2 U1.1 U1.4 U2.6 U3.7 U3.A1 U3.A2 U3.A3 U3.A4 U4.27 U6.17@1151.92,586.12 U7.17@1149.84,2184 U12.4 U15.3 U16.3 U17. U17.25 U17.26 U17.27 U17.28 U17.29 U17.30 U17.32 U17.33 U17.34 U17.35 U17.37 U17.38 U17.39 U17.40 U17.42 U17.46 U17.47 U17.48 U17.49 U17.51 U17.52 U17.53 U17.54 U18.2 U18.10 U21.6 U21.7 Y4.5

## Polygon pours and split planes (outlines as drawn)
VS+_CHB on L6_Bottom Layer "L6_BOTTOM_LAYER_VS+_CHB_P136" (solid, remove dead copper, pour order 136): 1309.32,2118.12 1309.32,2272 1189.32,2272 1189.32,2118.12
-0.23V_CHB on L6_Bottom Layer "L6_BOTTOM_LAYER_-0.23V_CHB_P138" (solid, remove dead copper, pour order 138): 1111.17,2117.99 1111.17,2274.54 941,2274.54 878,2274.54 878,2117.99
NetC27_1 on L6_Bottom Layer "L6_BOTTOM_LAYER_NETC27_1_P142" (solid, remove dead copper, pour order 142): 2161.04,977.1 2161.04,503.38 2259,503.38 2259,552 2259,806.31 2315.65,896 2457,896 2457,977.1
-0.23V_CHA on L6_Bottom Layer "L6_BOTTOM_LAYER_-0.23V_CHA_P128" (solid, pour order 128): 1743,652 1743,407.78 1552.18,407.78 1552.68,518.43 1190.45,520 1190.45,652
VS+_CHA on L6_Bottom Layer "L6_BOTTOM_LAYER_VS+_CHA_P126" (solid, remove dead copper, pour order 126): 992.45,652 992.45,523 1112.45,523 1112.45,652
GND on L2_GND1 "L2_GND1_GND_P046" (solid, remove dead copper, pour order 46): 0,2750 1140,2750 4000,2750 4000,0 1409.75,0 0,0 0,1482.45
GND on L4_Plane "L4_PLANE_GND_P116" (solid, remove dead copper, pour order 116): 3381,683 3381,12.51 3980,12.51 3980,2395.51 3980,2722.51 3381,2722.51
+3.3V on L4_Plane "L4_Plane-+3.3V" (solid, remove dead copper, pour order 147): 889,0 1840,0 3371,0 3371,2734 2170,2734 2166,2730 2166,2342.91 1123.91,2342.91 1123.91,2335.11 0,2335.11 0,2122.73 1123.91,2122.73 1123.91,1991 1489,1991 1489,2105.37 1837.5,2105.37 1840,704 889,704
AVDD on L4_Plane "L4_PLANE_AVDD_P039" (solid, remove dead copper, pour order 39): 20,2123.81 1110,2123.81 1110,1511 1253.72,1511 1254,1155 1383,1155 1820.32,717.68 886,717.68 886,0 20,0
+5V on L4_Plane "L4_PLANE_+5V_P122" (solid, remove dead copper, pour order 122): 2192,2342.91 0,2342.91 0,2742 2192,2742
IOVDD on L4_Plane "L4_Plane-IOVDD" (solid, remove dead copper, pour order 143): 1358.95,1163 1396.41,1163 1807.41,752 1824,752 1824,1984.2 1824.36,1984.2 1824.36,2106.07 1495.91,2106.11 1495.91,1984.54 1350,1984.54 1350,1984.2 1123.76,1984.2 1123.76,1524.08 1255.22,1524.08 1255.22,1459.65 1255.22,1159.78 1358.94,1161.2
-0.23V_CHB on L1_Top Layer "L1_TOP_LAYER_-0.23V_CHB_P140" (solid, remove dead copper, pour order 140): 787,2274.92 787,2177 831,2177 831,2117 940,2117 940,2275.08
GND on L5_GND2 "L5_GND2_GND_P120" (solid, remove dead copper, pour order 120): 0,2750 4000,2750 4000,0 0,0
GND on L3_Signal "L3_SIGNAL_GND_P145" (solid, remove dead copper, pour order 145): 0,2750 1140,2750 4000,2750 4000,0 1409.75,0 0,0 0,1482.45
-0.23V_CHB on L3_Signal "L3_SIGNAL_-0.23V_CHB_P144" (solid, pour order 144): 0,2342.91 0,2123.81 1123.91,2123.81 1123.91,2350.9 0,2350.9

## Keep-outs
Keep-Out Layer:
  text ".Layer_Name" at 577,-1885.49 h60

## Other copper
L1_Top Layer:
  rectangle net NetC24_2: 932.44,1353.65 946.44,1365.65
  rectangle net GND: 992.44,1352.65 1004.44,1365.65
  region net +3.3V: 361.07,2175.01 361,2175.01 361,2105 425,2105 425,2175
  region net VREF: 1097,1426.79 1092.21,1426.79 1082,1437 1035,1437 1035,1452.44 1084.57,1452.44 1084.57,1441.43 1092.4,1433.6 1097,1433.6
  text ".Layer_Name" at 577,-1885.49 h60
L3_Signal:
  text ".Layer_Name" at 577,-1880.49 h60
L4_Plane:
  text ".Layer_Name" at 577,-1880.49 h60
L2_GND1:
  pour cut-out: 1479.35,0 1479.35,214 1578.38,214 1578.38,0
  pour cut-out: 729.35,0 729.35,214 828.38,214 828.38,0
  pour cut-out: 1576.78,2750 1576.78,2536 1477.75,2536 1477.75,2750
  pour cut-out: 805.78,2750 805.78,2536 706.75,2536 706.75,2750
  pour cut-out: 0,1033.03 214,1033.03 214,934 0,934
  pour cut-out: 913.76,1567.3 930.26,1567.3 952.24,1567.3 952.24,1585 913.76,1585
  pour cut-out: 1216.64,1675 1216.64,1779 1285.36,1779 1285.36,1675.02 1285.39,1675
  pour cut-out: 1016,1675 1016,1779 1084.73,1779 1084.73,1675.02 1084.75,1675
  pour cut-out: 1216.8,2038.5 1216.8,2142.5 1285.52,2142.5 1285.52,2038.53 1285.54,2038.5
  pour cut-out: 1217.07,1875.48 1217.07,1979.48 1285.8,1979.48 1285.8,1875.5 1285.82,1875.48
  pour cut-out: 1117.05,1875.5 1117.05,1979.5 1185.77,1979.5 1185.77,1875.53 1185.8,1875.5
  pour cut-out: 1116.8,2038.5 1116.8,2142.5 1185.52,2142.5 1185.52,2038.53 1185.54,2038.5
  pour cut-out: 1016.8,2038.5 1016.8,2142.5 1085.52,2142.5 1085.52,2038.53 1085.54,2038.5
  pour cut-out: 1017.3,1875.5 1017.3,1979.5 1086.02,1979.5 1086.02,1875.53 1086.04,1875.5
  pour cut-out: 1016.64,2239 1016.64,2343 1085.36,2343 1085.36,2239.02 1085.39,2239
  pour cut-out: 977.75,1589 994.25,1589 994.25,1607.5 977.75,1607.5
  pour cut-out: 934,1684 934,1664 972,1664 972,1684
  pour cut-out: 960.52,1544.3 977.02,1544.3 977.02,1565.5 999,1565.5 999,1608.5 960.52,1608.5
  pour cut-out: 1219,417.64 1219,522 1288.54,522 1288.54,417.64
  pour cut-out: 1019,618 1019,722 1087.73,722 1087.73,618.02 1087.75,618
  pour cut-out: 1019,740 1019,844 1087.73,844 1087.73,740.02 1087.75,740
  pour cut-out: 1119,740 1119,844 1187.73,844 1187.73,740.02 1187.75,740
  pour cut-out: 1118.75,618 1118.75,722 1187.48,722 1187.48,618.02 1187.5,618
  pour cut-out: 1218.77,617.98 1218.77,721.98 1287.5,721.98 1287.5,618 1287.52,617.98
  pour cut-out: 1219,740 1219,844 1287.73,844 1287.73,740.02 1287.75,740
  pour cut-out: 1218.5,939 1218.5,1044 1287.23,1044 1287.23,939.02
  pour cut-out: 1018.73,938.99 1018.73,1044 1088.23,1044 1088.23,939.01
  pour cut-out: 577.99,1295.36 685.12,1295.36 685.12,1226.64 578.01,1226.64
  pour cut-out: 577.99,1495.36 685.13,1495.36 685.13,1426.64 578.01,1426.64
  pour cut-out: 378,1295 485,1295 485,1226.27 378.02,1226.27
  pour cut-out: 0,1783.03 214,1783.03 214,1684 0,1684
  text ".Layer_Name" at 577,-1880.49 h60
L5_GND2:
  text ".Layer_Name" at 577,-1880.49 h60
L6_Bottom Layer:
  region net +5V: 503.18,2473.8 479.56,2473.8 479.56,2366.11 479.56,2360.94 517.35,2360.94 517.35,2384.56 503.18,2384.56 503.18,2412.91
  region net NetC71_2: 479.48,2274 517.28,2274 517.28,2202.5 517.27,2140.31 569.5,2140.31 569.5,2116.69 493.65,2116.69 493.65,2167.35 493.65,2230.07 479.48,2230.07 479.48,2260.32
  region net NetC78_1: 1582.87,2039.91 1582.87,2008.42 1723.69,2008.42 1723.69,2139 1684.31,2139 1684.31,2040 1677.85,2040
  region net NetC72_2: 1568.61,2208.02 1606.41,2208.02 1606.41,2136.53 1606.41,2060.53 1582.79,2060.53 1582.79,2101.37 1582.79,2164.09 1568.61,2164.09 1568.61,2194.34
  region net +5V: 1592.31,2407.83 1568.69,2407.83 1568.69,2300.13 1568.69,2294.96 1606.49,2294.96 1606.49,2318.58 1592.31,2318.58 1592.31,2346.93
  text ".Layer_Name" at 577,-1885.49 h60

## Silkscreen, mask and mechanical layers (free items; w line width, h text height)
Top Overlay:
  lines w5: 1370,1330 1730,1330 1730,1570 1370,1570 1370,1330 ; 1400,990 1680,990 1680,1260 1400,1260 1400,990
  lines w7: 850,1270 860,1280 870,1290 ; 870,1220 870,1290 ; 890,1270 870,1290 ; 1290,1170 1280,1180 1270,1190 ; 1290,1210 1270,1190 ; 1290,1540 1280,1550 1270,1560 ; 1290,1580 1270,1560 ; 1370,1560 1270,1560 ; 1390,1190 1270,1190 ; 2280,2590 2300,2610 2300,2650 2310,2660 2350,2660 ; 2330,2640 2350,2660 ; 2330,2680 2350,2660 ; 2580,2580 2600,2600 ; 2620,2580 2600,2600 ; 2670,2510 2620,2510 2600,2530 2600,2600
  text "5V_EXT" at 2060,2530 h50
  text "GND" at 1810.59,2518 h50
  text "USB 5V" at 2740,2420 h50 r90
  text "BINn" at 1450,2410 h50
  text "BINp" at 680,2406.66 h50
  text "-0.23V_B" at 62,2337.19 h50
  text "AVDD" at 290,2142 h40 r90
  text "GND" at 30,2140 h40
  text "PDN_SYNC" at 20,1987 h40
  text "+3.3VB" at 1362,1874 h50
  text "VREF" at 719,1855 h50
  text "ADC36xx" at 3013.73,1786.27 h50
  text "CLKp" at 300,1726.66 h50
  text "DC134E" at 3015.37,1714.19 h50
  text "IOVDD" at 1578,1589 h50
  text "PLL LOCK" at 2112,1095 h50
  text "CLKn" at 300,1090 h50
  text "GND" at 456.95,1016 h50
  text "REFBUF" at 307,915 h50
  text "GND" at 1492.33,894 h50
  text "VCM" at 810,850 h40
  text "AVDD" at 406.97,815 h50
  text "CDC / 3.3V" at 1950,770 h50
  text "CLK3" at 2738.66,652.09 h50
  text "CLK4" at 3000,650 h50
  text "+3.3VA" at 740,640 h40
  text "-0.23V_A" at 1640,620 h50
  text "AVDD" at 580,540 h50
  text "GND" at 90,510 h40
  text "Reset" at 260,350 h50
  text "AINp" at 700,326.66 h50
  text "AINn" at 1450,310 h50
  text "DCLKIN" at 3060,130 h50
  text ".Layer_Name" at 577,-1885.49 h60
Bottom Overlay:
  lines w7: 273,1697 273,1771 ; 1450,2410 1470,2390 ; 1470,2500 1470,2390 ; 1490,2410 1470,2390
  text ".Layer_Name" at 577,-1885.49 h60
Top Paste:
  text ".Layer_Name" at 577,-1885.49 h60
Bottom Paste:
  text ".Layer_Name" at 577,-1885.49 h60
Top Solder:
  text ".Layer_Name" at 577,-1885.49 h60
  text ".Layer_Name" at 577,-1885.49 h60
Bottom Solder:
  text ".Layer_Name" at 577,-1885.49 h60
Drill Guide:
  text ".Layer_Name" at 577,-1885.49 h60
M1 Board Outline:
  the board outline again, w7
  text ".Layer_Name" at 577,-1885.49 h60
M2 Board Dimensions:
  rectangle: 0,-1302 125,-1177
  rectangle: 125,-1427 500,-1302
  lines w7: 0,-1302 1000,-1302 ; 125,-1427 125,-1177 ; 250,-1427 250,-1177 ; 500,-1427 500,-1177 ; 750,-1427 750,-1177 ; 0,-1427 1000,-1427 1000,-1177 0,-1177 0,-1427
  text ".Layer_Name" at 577,-1885.49 h60
M3 3D STEP Top:
  text ".Layer_Name" at 577,-1885.49 h60
M4 3D STEP Bottom:
  text ".Layer_Name" at 577,-1885.49 h60
M5 Assembly Top:
  lines w10: -292,-1957.17 6308,-1957.17 ; -292,-1753.83 6310,-1753.83 ; -292,-1550.5 -292,-2160.5 3713,-2160.5 6310,-2160.5 6310,-1550.5 -291.5,-1550.5 -291.5,-2160.5 1284,-2160.5 ; 2173,-2160.5 2173,-1550.5 ; 3440,-1753.83 3440,-1550.5 ; 4280,-1753.83 4280,-1550.5 ; 4902,-2167 4902,-1964.17
  text "COMPONENTS MARKED 'DNP' SHOULD NOT BE POPULATED." at 1153.5,-1345.5 h60
  text "ASSEMBLY VARIANT:" at 1153,-1461 h60
  text ".VariantName" at 2189,-1461 h60
  text "PCB VIEWED FROM TOP SIDE" at -228.5,-1682.67 h60
  text "BOARD #:" at 2248,-1682.67 h60
  text ".PRJ_Number" at 2793.5,-1682.67 h60
  text "REV:" at 3638,-1682.67 h60
  text ".PCB_Rev" at 3929.5,-1682.67 h60
  text "SVN REV:" at 4476,-1682.67 h60
  text ".VersionControl_RevNumber" at 4982,-1682.67 h60
  text "TID #:" at 2248,-1886 h60
  text ".TID" at 2793.5,-1886 h60
  text "PLOT NAME =" at -228.5,-2091.34 h60
  text ".plot_File_Name" at 577,-2091.34 h60
  text "GENERATED    :" at 2250,-2091.34 h60
  text ".Print_Date" at 3119.5,-2091.34 h60
  text ".Print_Time" at 3848.5,-2091.34 h60
  text "TEXAS INSTRUMENTS" at 5113,-2091.34 h60
M6 Assembly Bottom:
  lines w10: -292.5,-1754.33 6309.5,-1754.33 ; -290.5,-1957.67 6309.5,-1957.67 ; 1115.5,-2167.5 1115.5,-1964.67 ; 1737.5,-1754.33 1737.5,-1551 ; 2577.5,-1754.33 2577.5,-1551 ; 3844.5,-2161 3844.5,-1551 ; 4733.5,-2161 6309,-2161 6309,-1551 -292.5,-1551 -292.5,-2161 2304.5,-2161 6309.5,-2161 6309.5,-1551
  text "COMPONENTS MARKED 'DNP' SHOULD NOT BE POPULATED." at 6102,-1345 h60
  text ".VariantName" at 5058,-1461 h60
  text "ASSEMBLY VARIANT:" at 6097,-1461 h60
  text ".VersionControl_RevNumber" at 1035.5,-1683.17 h60
  text "SVN REV:" at 1541.5,-1683.17 h60
  text ".PCB_Rev" at 2088,-1683.17 h60
  text "REV:" at 2379.5,-1683.17 h60
  text ".PRJ_Number" at 3224,-1683.17 h60
  text "BOARD #:" at 3769.5,-1683.17 h60
  text "PCB VIEWED FROM BOTTOM SIDE" at 6246,-1683.17 h60
  text ".TID" at 3224,-1886.5 h60
  text "TID #:" at 3769.5,-1886.5 h60
  text "TEXAS INSTRUMENTS" at 904.5,-2091.84 h60
  text ".Print_Time" at 2169,-2091.84 h60
  text ".Print_Date" at 2898,-2091.84 h60
  text "GENERATED    :" at 3767.5,-2091.84 h60
  text ".plot_File_Name" at 5440.5,-2091.84 h60
  text "PLOT NAME =" at 6246,-2091.84 h60
M9 Title Sheet:
  drawing of 57 lines, arcs and shapes, not listed
  text "1" at 739.84,7009.5 h70
  text "2" at 3235.5,7009.5 h70
  text "3" at 5724.84,7009.5 h70
  text "4" at 8231.51,7009.5 h70
  text "5" at 10730.5,7009.5 h70
  text "6" at 13235.5,7009.5 h70
  text "A" at -416.5,5866.5 h70
  text "A" at 14383.5,5866.5 h70
  text "B" at -416.5,3486.5 h70
  text "B" at 14383.5,3486.5 h70
  text "C" at -416.5,1111.5 h70
  text "C" at 14383.5,1111.5 h70
  text "PROJECT TITLE:" at 11343.5,-749.5 h45
  text "ADC3683EVM" at 11393.5,-882.83 h70
  text "DESIGNED FOR:" at 11343.5,-1050.5 h45
  text ".PRJ_Customer" at 11393.5,-1190.5 h70
  text "D" at -416.5,-1258.5 h70
  text "D" at 14383.5,-1258.5 h70
  text "FILE NAME:" at 11343.5,-1350.5 h45
  text ".PCB_File_Name_No_Path" at 11393.5,-1470.5 h70
  text "Texas Instruments (TI) and/or its licensors do not warrant the accuracy or completeness of this specification" at 6374,-1632.34 h45
  text "ENGINEER:" at 11343.5,-1640.5 h45
  text "LAYOUT BY:" at 12848.5,-1640.5 h45
  text "or any information contained therein. TI and/or its licensors do not warrant that this design will meet" at 6329.01,-1745 h45
  text "Daniel Brock" at 11393.5,-1795.49 h70
  text "Daniel Brock" at 12899,-1795.49 h70
  text "the specifications, will be suitable for your application or fit for any particular purpose, or will operate in" at 6329.01,-1857.67 h45
  text ".Layer_Name" at 577,-1885.49 h60
  text "ALTIUM DESIGNER VERSION:" at 12848.5,-1950.5 h45
  text "an implementation. TI and/or its licensors do not warrant that the design is production worthy. You should" at 6329.01,-1970.33 h45
  text "completely validate and test your design implementation to confirm the system functionality for your application." at 6374,-2083 h45
  text ".print_Scale" at 11393.5,-2083.83 h70
  text ".Application_BuildNumber" at 12899,-2083.83 h70
  text "1" at 739.84,-2290.5 h70
  text "2" at 3235.5,-2290.5 h70
  text "3" at 5724.84,-2290.5 h70
  text "4" at 8231.51,-2290.5 h70
  text "5" at 10730.5,-2290.5 h70
  text "6" at 13235.5,-2290.5 h70
M10 Fab Notes:
  drawing of 191 lines, arcs and shapes, not listed
  text "NOTE:" at -98,5482 h100
  text "DESIGN INFORMATION" at 12382.02,5329.17 h60
  text "1. 5 MIL DIFFERENTIAL PAIRS  ON  L1 ARE  100 OHMS  +/- 10%" at -50,5294 h70
  text "5" at 12781.5,5199.1 h60
  text "MIN. TRACK WIDTH:" at 11737.46,5197.05 h60
  text "MIL" at 12988.46,5197.05 h60
  text "2. ALL  VIA HOLES  NEED TO BE TENTED ON TOP AND BOTTOM SIDE." at -63,5164 h70
  text "MIN. CLEARANCE:" at 11737.46,5072.92 h60
  text "mil" at 12988.46,5072.92 h60
  text "5" at 12746.5,5068 h60
  text "3. VIA HOLES UNDER IC U2 NEED TO BE FILLED WITH SOLDER MASK TO PREVENT SOLDER PASTE FLOW INTO VIAS." at -69,5001 h70
  text "MIN. VIA PAD SIZE:" at 11737.46,4948.8 h60
  text "MIL" at 13064,4949.42 h60
  text "18" at 12766,4947 h60
  text "IPC Class 2 specifications" at 12432.46,4818.9 h60
  text "MINIMUM ANNULAR RING" at 11408.23,4810.67 h60
  text "PER" at 11608.23,4700.55 h60
  text "IPC-D-275 CLASS 2 LEVEL C" at 11828.23,4700.54 h60
  text "MIL, HOLES" at 13316.46,4600.07 h60
  text "+/-" at 12924,4591.48 h60
  text "+/-" at 13778,4591.48 h60
  text "REGISTRATION TOLERANCES:" at 11408.23,4590.42 h60
  text "METAL" at 12608,4590.42 h60
  text "5" at 13184.2,4590.42 h60
  text "3" at 14017.2,4590.42 h60
  text "MIL" at 14133.46,4590.42 h60
  text "HOLE SIZE TOLERANCE (UNLESS OTHERWISE SPECIFIED):" at 11408.23,4492.1 h60
  text "+/-" at 13778,4489.23 h60
  text "3" at 14017.2,4488.17 h60
  text "MIL" at 14133.46,4488.17 h60
  text "MATERIAL:" at 11333.46,4350.52 h60
  text "FR-4 High Tg" at 12319.9,4222 h60
  text "X" at 13068,4220 h60
  text "370HR" at 13586,4210 h60
  text "FR-408" at 11754.46,4209.49 h60
  text "OTHER" at 13242.46,4209.49 h60
  text "62 MIL +/-10%" at 12074.56,4066.46 h60
  text "X" at 11954.46,4064.01 h60
  text "THICKNESS:" at 11408.23,4058.24 h60
  text "OTHER" at 13359.46,4058.24 h60
  text "TOLERANCE:" at 11408.23,3919.92 h60
  text "X" at 12256.46,3919.92 h60
  text "ANSI IPC-6012 TYPE 3 CLASS 2" at 12434.48,3919.92 h60
  text "OTHER +/-" at 12434.46,3775.73 h60
  text "BOW & TWIST:" at 11408.23,3630.54 h60
  text "X" at 12256.46,3630.54 h60
  text "ANSI IPC-6012 TYPE 3 CLASS 2" at 12434.48,3630.54 h60
  text "OTHER +/-" at 12434.46,3483.85 h60
  text "DRILLING:" at 11333.46,3353.23 h60
  text "NC_DRILL FILES" at 13094.46,3248.04 h60
  text "REFERENCE:" at 11408.23,3244.1 h60
  text "X" at 12065.46,3244.01 h60
  text "AS SHOWN" at 12243.46,3244.1 h60
  text "X" at 12966.46,3244.1 h60
  text "OTHER" at 13392.46,3101.85 h60
  text "PTH COPPER THICKNESS:" at 11407.91,3098.32 h60
  text "X" at 12547.14,3098.32 h60
  text "20-30 um" at 12675.14,3098.32 h60
  text "BOARD FINISH:" at 11333.46,2950.73 h60
  text "SILKSCREEN:" at 11488.68,2840.6 h60
  text "X" at 12446.46,2840.6 h60
  text "TOP" at 12563.46,2840.6 h60
  text "X" at 12956.46,2840.6 h60
  text "BOTTOM" at 13074.46,2840.6 h60
  text "SILKSCREEN COLOR:" at 11488.68,2685.41 h60
  text "X" at 12445.46,2685.41 h60
  text "WHITE" at 12563.46,2685.41 h60
  text "OTHER" at 13074.46,2685.41 h60
  text "GREEN" at 12694.46,2541.96 h60
  text "X" at 13165.46,2541.96 h60
  text "OTHER" at 13312.46,2541.96 h60
  text "RED" at 13823.96,2541.96 h60
  text "SOLDER RESIST COLOR:" at 11488.68,2535.1 h60
  text "MATTE" at 12694.46,2387.71 h60
  text "X" at 13176.46,2387.71 h60
  text "SEMI-GLOSS" at 13312,2387.07 h60
  text "IMMERSION GOLD (ENIG)" at 12394.46,2214.94 h60
  text "ENEPIG" at 13732,2207.72 h60
  text "SURFACE FINISH:" at 11333.46,2206.72 h60
  text "X" at 13583.96,2204.41 h60
  text "IMM. TIN/SILVER OR EQUIV" at 11663,2069.4 h60
  text "OTHER" at 13094.46,2065.47 h60
  text "ARRAY/PANEL:" at 11333.46,1910.09 h60
  text "CUT AND TRIM PER M1 BOARD OUTLINE" at 12394.46,1901.87 h60
  text "X" at 12215,1899.13 h60
  text "N.C. ROUTE" at 12394.46,1765.9 h60
  text "V. SCORE" at 13260.46,1765.9 h60
  text "CERTIFICATION:" at 11333.46,1636.77 h60
  text "MATERIALS AND WORKMANSHIP FOR ALL PCBS" at 12058.46,1636.77 h60
  text "TO MEET OR EXCEED THE REQUIREMENTS OF:" at 12058.46,1542.71 h60
  text "X" at 11695.97,1414.08 h60
  text "ANSI IPC-A-600F CLASS ->" at 11823.96,1414.08 h60
  text "X" at 13471.97,1414.08 h60
  text "2" at 13581.96,1414.08 h60
  text "1" at 13266.96,1412.58 h60
  text "3" at 13935.96,1412.58 h60
  text "X" at 12507.97,1266.39 h60
  text "RoHS" at 12635.96,1266.39 h60
  text "OTHER" at 13280.36,1266.39 h60
  text "PER ORDER" at 13677.42,1266.39 h60
  text "ALL BOARDS MUST MEET OR EXCEED UL94-V0 REQUIREMENTS." at 11361,1112.57 h60
  text "PCB MUST BEAR THE UL94V-0 UL REGISTERED MATERIAL ID NUMBER" at 11361,996.5 h60
  text "ADDITIONAL REQUIREMENTS:" at 11333.46,827.08 h60
  text "MICROSECTION:" at 11408.23,719.95 h60
  text "YES" at 12313.96,719.95 h60
  text "REQUIRED" at 13175.46,575.62 h60
  text "BARE BOARD ELEC. TEST:" at 11408.23,572.76 h60
  text "NONE" at 12713.96,572.76 h60
  text "X" at 13057.46,572.76 h60
  text "PER ORDER" at 13767.46,572.76 h60
  text "XX MIL VIAS REQUIRE NON-CONDUCTIVE FILL AND PLANARIZE" at 11576.38,367.82 h59
  text "XX MIL VIAS REQUIRE CONDUCTIVE FILL AND PLANARIZE" at 11584.38,263.84 h60
  text "OUTER XX MIL TRACES REQUIRE 50 OHM SINGLE-ENDED IMPEDANCE" at 11583.39,100.46 h58
  text "LAYER 2 & 3 (INNER LAYERS) XX MIL WIDE, XX MIL SPACE / TRACES REQUIRE 100 OHM DIFFERENTIAL IMPEDANCE" at 11575.39,-135.26 h60
  text ".Layer_Name" at 577,-1885.49 h60
M11 Gerber Information:
  lines w10: -292,-1957.17 6308,-1957.17 ; -292,-1753.83 6310,-1753.83 ; -292,-1550.5 -292,-2160.5 3713,-2160.5 6310,-2160.5 6310,-1550.5 -291.5,-1550.5 -291.5,-2160.5 1284,-2160.5 ; 2173,-2160.5 2173,-1550.5 ; 3440,-1753.83 3440,-1550.5 ; 4280,-1753.83 4280,-1550.5 ; 4902,-2167 4902,-1964.17
  text "ALL ARTWORK VIEWED FROM TOP SIDE" at -228.5,-1682.67 h60
  text "BOARD #:" at 2248,-1682.67 h60
  text ".PRJ_Number" at 2793.5,-1682.67 h60
  text "REV:" at 3638,-1682.67 h60
  text ".PCB_Rev" at 3929.5,-1682.67 h60
  text "SVN REV:" at 4476,-1682.67 h60
  text ".VersionControl_RevNumber" at 4982,-1682.67 h60
  text "LAYER NAME =" at -228.5,-1885.49 h60
  text "TID #:" at 2248,-1886 h60
  text ".TID" at 2793.5,-1886 h60
  text "PLOT NAME =" at -228.5,-2091.34 h60
  text ".PRJ_Number" at 577,-2091.34 h60
  text "GENERATED    :" at 2250,-2091.34 h60
  text ".Print_Date" at 3119.5,-2091.34 h60
  text ".Print_Time" at 3848.5,-2091.34 h60
  text "TEXAS INSTRUMENTS" at 5113,-2091.34 h60
M12 Stackup:
  drawing of 399 lines, arcs and shapes, not listed
  text "Layer" at 5717.49,5401.6 h60
  text "Name" at 6127.4,5401.6 h60
  text "Material" at 7117.13,5401.6 h60
  text "Thickness" at 7976.89,5401.6 h60
  text "Constant" at 8626.73,5401.6 h60
  text "Board Layer Stack" at 9196.59,5401.6 h60
  text "Top Overlay" at 6127.4,5281.6 h60
  text "Top Solder" at 6127.4,5161.6 h60
  text "Solder Resist" at 7117.13,5161.6 h60
  text "0.50mil" at 7976.89,5161.6 h60
  text "3.5" at 8626.73,5161.6 h60
  text "1" at 5717.49,5041.6 h60
  text "L1_Top Layer" at 6127.4,5041.6 h60
  text "1.40mil" at 7976.89,5041.6 h60
  text "Dielectric 1" at 6127.4,4921.6 h60
  text "FR4-370HR" at 7117.13,4921.6 h60
  text "8.00mil" at 7976.89,4921.6 h60
  text "4.17" at 8626.73,4921.6 h60
  text "2" at 5717.49,4801.6 h60
  text "L2_GND1" at 6127.4,4801.6 h60
  text "1.40mil" at 7976.89,4801.6 h60
  text "Dielectric 2" at 6127.4,4681.6 h60
  text "FR4-370HR" at 7117.13,4681.6 h60
  text "14.00mil" at 7976.89,4681.6 h60
  text "4.05" at 8626.73,4681.6 h60
  text "3" at 5717.49,4561.6 h60
  text "L3_Signal" at 6127.4,4561.6 h60
  text "1.40mil" at 7976.89,4561.6 h60
  text "Dielectric 3" at 6127.4,4441.6 h60
  text "FR4-370HR" at 7117.13,4441.6 h60
  text "8.00mil" at 7976.89,4441.6 h60
  text "4.17" at 8626.73,4441.6 h60
  text "4" at 5717.49,4321.6 h60
  text "L4_Plane" at 6127.4,4321.6 h60
  text "1.40mil" at 7976.89,4321.6 h60
  text "Dielectric 4" at 6127.4,4201.6 h60
  text "FR4-370HR" at 7117.13,4201.6 h60
  text "14.00mil" at 7976.89,4201.6 h60
  text "4.05" at 8626.73,4201.6 h60
  text "5" at 5717.49,4081.6 h60
  text "L5_GND2" at 6127.4,4081.6 h60
  text "1.40mil" at 7976.89,4081.6 h60
  text "Dielectric 5" at 6127.4,3961.6 h60
  text "FR4-370HR" at 7117.13,3961.6 h60
  text "8.00mil" at 7976.89,3961.6 h60
  text "4.17" at 8626.73,3961.6 h60
  text "6" at 5717.49,3841.6 h60
  text "L6_Bottom Layer" at 6127.4,3841.6 h60
  text "1.40mil" at 7976.89,3841.6 h60
  text "Bottom Solder" at 6127.4,3721.6 h60
  text "Solder Resist" at 7117.13,3721.6 h60
  text "0.50mil" at 7976.89,3721.6 h60
  text "3.5" at 8626.73,3721.6 h60
  text "Bottom Overlay" at 6127.4,3601.6 h60
  text "Total board thickness:" at 5717.49,3481.6 h60
  text "61.40mil" at 7976.89,3481.6 h60
  text ".Layer_Name" at 577,-1885.49 h60
M13 Component Bodies Top:
  text ".Layer_Name" at 577,-1885.49 h60
M14 Component Bodies Bottom:
  text ".Layer_Name" at 577,-1885.49 h60
M15 Courtyards Top:
  text ".Layer_Name" at 577,-1885.49 h60
M16 Courtyards Bottom:
  text ".Layer_Name" at 577,-1885.49 h60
